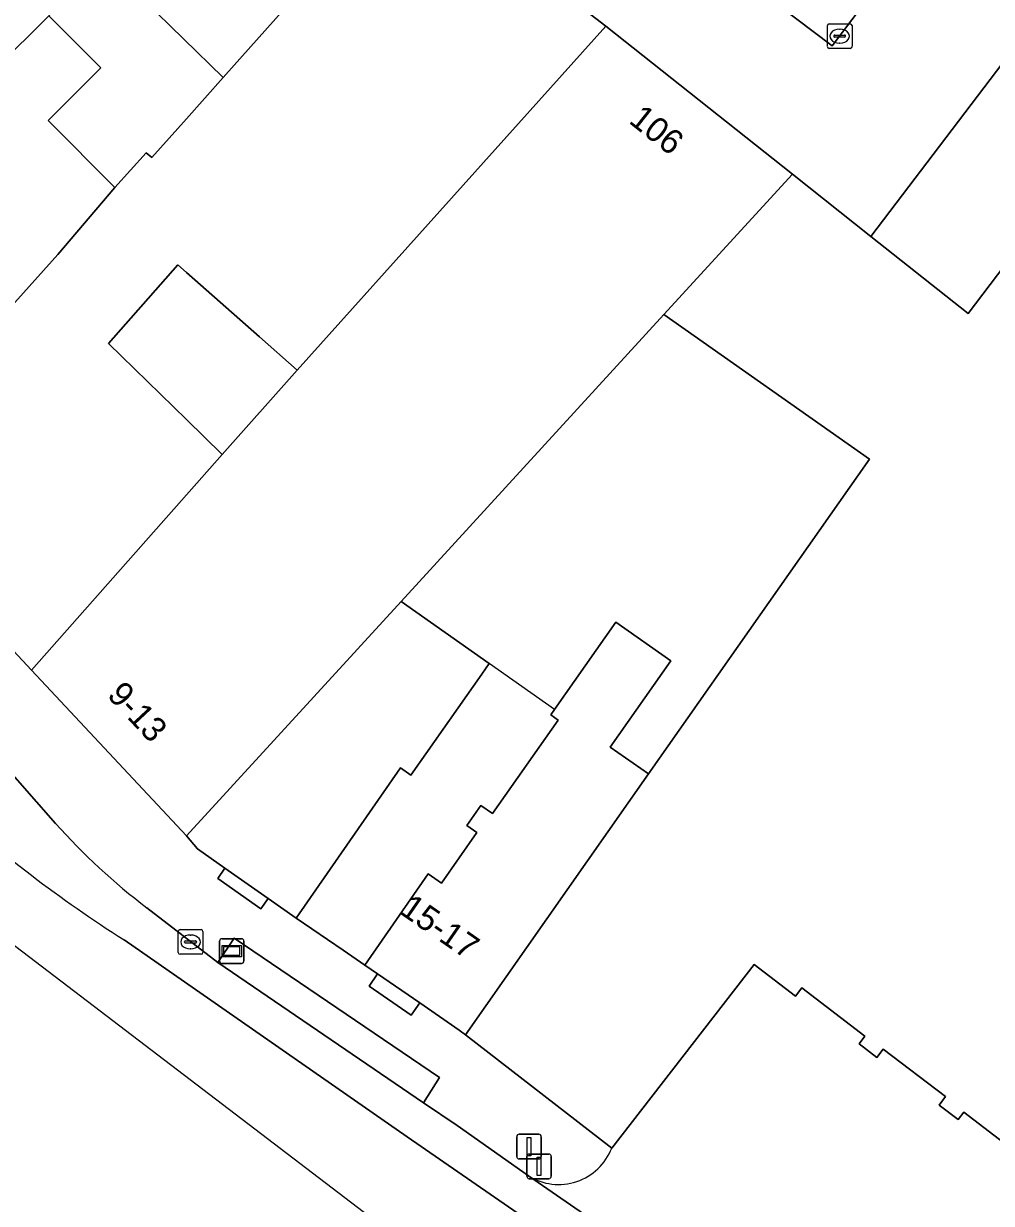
# Model space of a CAD drawing. Extents: x 160663 to 161506, y 382245 to 383291.
# Drawn here: x 160993.39 to 161032.66, y 382793.4 to 382841.23 of the extents above; entities that cross this region are included whole.
import ezdxf

# ---------------------------------------------------------------- set-up
doc = ezdxf.new("R2010")
doc.units = 0
for name, color, linetype in [('IMGEO_Erf', 7, 'Continuous'), ('IMGEO_Kolk', 7, 'Continuous'), ('IMGEO_Lichtmast', 7, 'Continuous'), ('IMGEO_Pand', 7, 'Continuous'), ('IMGEO_Pand_nummerreeks', 7, 'Continuous'), ('IMGEO_Pand_overbouw', 7, 'Continuous'), ('IMGEO_Parkeervlak_open', 7, 'Continuous'), ('IMGEO_Rijbaan_lokaal_gesloten', 7, 'Continuous'), ('IMGEO_Rijbaan_lokaal_open', 7, 'Continuous'), ('IMGEO_Verkeersregelinstallatiepaal', 7, 'Continuous'), ('IMGEO_Voetpad_open', 7, 'Continuous'), ('IMGEO_Wegwijzer', 7, 'Continuous')]:
    doc.layers.add(name, color=color, linetype=linetype)

msp = doc.modelspace()

# ---------------------------------------------------------------- linework, layer by layer
at = {"layer": 'IMGEO_Erf'}
for points in [[(161002.961, 382828.523), (161000, 382831.142), (160999.651, 382831.451), (160996.836, 382828.259), (161000, 382825.179), (161001.456, 382823.762), (161004.488, 382827.173)], [(161019.369, 382829.436), (161008.711, 382817.804), (161012.288, 382815.292), (161011.979, 382814.851), (161009.105, 382810.759), (161008.688, 382811.051), (161004.447, 382804.966), (161006.356, 382803.662), (161007.234, 382803.062), (161009.806, 382806.765), (161010.347, 382806.385), (161011.785, 382808.433), (161011.377, 382808.72), (161011.949, 382809.533), (161012.418, 382809.204), (161015.08, 382812.993), (161014.777, 382813.205), (161014.926, 382813.417), (161017.414, 382816.96), (161019.648, 382815.391), (161017.196, 382811.899), (161018.747, 382810.81), (161027.712, 382823.575)]]:
    msp.add_lwpolyline(points, close=True, dxfattribs=at)
at = {"layer": 'IMGEO_Kolk'}
for p, q in [((161026, 382840.292), (161026, 382841.144)), ((161026.075, 382841.218), (161026.927, 382841.218)), ((161026.488, 382840.998), (161026.513, 382840.998)), ((161027.001, 382841.144), (161027.001, 382840.292)), ((161026.259, 382840.712), (161026.259, 382840.724)), ((161026.697, 382840.675), (161026.299, 382840.675)), ((161026.302, 382840.761), (161026.7, 382840.761)), ((161026.511, 382840.438), (161026.486, 382840.438)), ((161026.743, 382840.724), (161026.743, 382840.712)), ((161026.927, 382840.218), (161026.075, 382840.218)), ((160999.668, 382803.57), (160999.668, 382804.422)), ((160999.743, 382804.496), (161000.595, 382804.496)), ((161000.669, 382804.422), (161000.669, 382803.57)), ((160999.927, 382803.99), (160999.927, 382804.002)), ((161000.365, 382803.953), (160999.967, 382803.953)), ((160999.97, 382804.039), (161000.368, 382804.039)), ((161000.156, 382804.276), (161000.181, 382804.276)), ((161000.411, 382804.002), (161000.411, 382803.99)), ((161000.595, 382803.496), (160999.743, 382803.496)), ((161000.179, 382803.716), (161000.154, 382803.716))]:
    msp.add_line(p, q, dxfattribs=at)
for points in [[(161026, 382840.292), (161026, 382841.144)], [(161026.075, 382841.218), (161026.927, 382841.218)], [(161027.001, 382841.144), (161027.001, 382840.292)], [(161026.927, 382840.218), (161026.075, 382840.218)], [(160999.668, 382803.57), (160999.668, 382804.422)], [(160999.743, 382804.496), (161000.595, 382804.496)], [(161000.669, 382804.422), (161000.669, 382803.57)], [(161000.595, 382803.496), (160999.743, 382803.496)]]:
    msp.add_lwpolyline(points, dxfattribs=at)
for centre, radius, start, end in [((161026.077, 382841.142), 0.0765, 91.552, 178.448), ((161026.077, 382841.142), 0.0765, 91.552, 178.448), ((161026.925, 382841.142), 0.0765, 1.552, 88.448), ((161026.925, 382841.142), 0.0765, 1.552, 88.448), ((161026.299, 382840.721), 0.0403, 85.8775, 175.7526), ((161026.296, 382840.711), 0.0366, 178.938, 274.7102), ((161026.7, 382840.718), 0.043, 264.8664, 352.4533), ((161026.704, 382840.723), 0.0386, 1.7309, 96.639), ((161026.077, 382840.294), 0.0765, 181.552, 268.448), ((161026.077, 382840.294), 0.0765, 181.552, 268.448), ((161026.925, 382840.294), 0.0765, 271.552, 358.448), ((161026.925, 382840.294), 0.0765, 271.552, 358.448), ((160999.745, 382804.42), 0.0765, 91.552, 178.448), ((160999.745, 382804.42), 0.0765, 91.552, 178.448), ((161000.593, 382804.42), 0.0765, 1.552, 88.448), ((161000.593, 382804.42), 0.0765, 1.552, 88.448), ((160999.967, 382803.999), 0.0403, 85.8775, 175.7526), ((160999.964, 382803.989), 0.0366, 178.938, 274.7102), ((161000.368, 382803.996), 0.043, 264.8664, 352.4533), ((161000.372, 382804.001), 0.0386, 1.7309, 96.639), ((160999.745, 382803.572), 0.0765, 181.552, 268.448), ((160999.745, 382803.572), 0.0765, 181.552, 268.448), ((161000.593, 382803.572), 0.0765, 271.552, 358.448), ((161000.593, 382803.572), 0.0765, 271.552, 358.448)]:
    msp.add_arc(centre, radius, start, end, dxfattribs=at)
for centre, major_axis, ratio, start_param, end_param in [((161026.487, 382840.718), (-0.387, 0.002), 0.722429, 4.712389, 7.853982), ((161026.512, 382840.718), (-0.39, 0.002), 0.717154, 1.570796, 4.712389), ((161000.155, 382803.996), (-0.387, 0.002), 0.722429, 4.712389, 7.853982), ((161000.18, 382803.996), (-0.39, 0.002), 0.717154, 1.570796, 4.712389)]:
    msp.add_ellipse(centre, major_axis=major_axis, ratio=ratio, start_param=start_param, end_param=end_param, dxfattribs=at)
at = {"layer": 'IMGEO_Lichtmast'}
for p, q in [((161013.909, 382795.399), (161014.699, 382795.399)), ((161014.699, 382795.399), (161013.909, 382795.399)), ((161013.809, 382794.499), (161013.809, 382795.299)), ((161013.809, 382795.299), (161013.809, 382794.499)), ((161014.799, 382795.299), (161014.799, 382794.499)), ((161014.799, 382794.499), (161014.799, 382795.299)), ((161014.699, 382794.399), (161013.909, 382794.399)), ((161013.909, 382794.399), (161014.699, 382794.399))]:
    msp.add_line(p, q, dxfattribs=at)
msp.add_lwpolyline([(161014.229, 382795.274), (161014.379, 382795.274), (161014.379, 382794.524), (161014.229, 382794.524), (161014.229, 382795.274)], dxfattribs=at)
for centre, start, end in [((161013.909, 382795.299), 90, 180), ((161013.909, 382795.299), 90, 180), ((161014.699, 382795.299), 0, 90), ((161014.699, 382795.299), 360, 90), ((161013.909, 382794.499), 180, 270), ((161013.909, 382794.499), 180, 270), ((161014.699, 382794.499), 270, 0), ((161014.699, 382794.499), 270, 0)]:
    msp.add_arc(centre, 0.1, start, end, dxfattribs=at)
at = {"layer": 'IMGEO_Pand'}
for points in [[(161017.015, 382841.125), (161015.219, 382842.521), (161009.04, 382847.522), (161005.762, 382843.842), (161001.492, 382839.047), (161000, 382837.371), (160998.598, 382835.797), (160998.363, 382835.992), (160997.101, 382834.576), (160994.79, 382831.866), (160986.529, 382822.664), (160992.244, 382816.582), (160993.712, 382815.013), (161001.456, 382823.762), (161000, 382825.179), (160996.836, 382828.259), (160999.651, 382831.451), (161000, 382831.142), (161002.961, 382828.523), (161004.488, 382827.173)], [(160987.939, 382843.74), (160976.696, 382832.495), (160979.771, 382829.42), (160982.946, 382826.246), (160986.529, 382822.664), (160994.79, 382831.866), (160997.101, 382834.576), (160994.393, 382837.303), (160996.522, 382839.439), (160994.42, 382841.542), (160992.264, 382839.415)], [(161019.369, 382829.436), (161024.581, 382835.124), (161017.015, 382841.125), (161004.488, 382827.173), (161001.456, 382823.762), (160993.712, 382815.013), (161000, 382808.297), (161008.711, 382817.804)], [(161000, 382808.297), (161000.45, 382807.767), (161001.563, 382806.987), (161003.312, 382805.761), (161004.447, 382804.966), (161008.688, 382811.051), (161009.105, 382810.759), (161011.979, 382814.851), (161012.288, 382815.292), (161008.711, 382817.804)], [(161011.319, 382800.229), (161018.747, 382810.81), (161017.196, 382811.899), (161019.648, 382815.391), (161017.414, 382816.96), (161014.926, 382813.417), (161014.777, 382813.205), (161015.08, 382812.993), (161012.418, 382809.204), (161011.949, 382809.533), (161011.377, 382808.72), (161011.785, 382808.433), (161010.347, 382806.385), (161009.806, 382806.765), (161007.234, 382803.062), (161007.754, 382802.704), (161009.465, 382801.526), (161011.068, 382800.423)]]:
    msp.add_lwpolyline(points, close=True, dxfattribs=at)
msp.add_lwpolyline([(161034.089, 382832.61), (161031.709, 382829.469), (161027.763, 382832.6), (161024.581, 382835.124), (161019.369, 382829.436), (161027.712, 382823.575), (161018.747, 382810.81), (161011.319, 382800.229), (161017.252, 382795.641), (161023.035, 382803.078), (161024.709, 382801.803), (161024.961, 382802.132), (161027.524, 382800.182), (161027.284, 382799.867), (161028.011, 382799.313), (161028.268, 382799.649), (161030.791, 382797.726), (161030.53, 382797.383), (161031.303, 382796.794), (161031.532, 382797.094), (161033.969, 382795.23)], dxfattribs=at)
at = {"layer": 'IMGEO_Pand_overbouw'}
msp.add_lwpolyline([(161014.926, 382813.417), (161012.288, 382815.292), (161011.979, 382814.851), (161009.105, 382810.759), (161008.688, 382811.051), (161004.447, 382804.966), (161006.356, 382803.662), (161007.234, 382803.062), (161009.806, 382806.765), (161010.347, 382806.385), (161011.785, 382808.433), (161011.377, 382808.72), (161011.949, 382809.533), (161012.418, 382809.204), (161015.08, 382812.993), (161014.777, 382813.205)], close=True, dxfattribs=at)
at = {"layer": 'IMGEO_Parkeervlak_open'}
for points in [[(161026.197, 382840.33), (161050.071, 382871.893), (161041.959, 382877.99), (161018.147, 382846.412)], [(160987.817, 382852.376), (160985.729, 382850.234), (160983.615, 382848.065), (160987.939, 382843.74), (160992.264, 382839.415), (160994.42, 382841.542), (160996.662, 382843.754)]]:
    msp.add_lwpolyline(points, close=True, dxfattribs=at)
for points in [[(161033.969, 382795.23), (161031.532, 382797.094), (161031.303, 382796.794), (161030.53, 382797.383), (161030.791, 382797.726), (161028.268, 382799.649), (161028.011, 382799.313), (161027.284, 382799.867), (161027.524, 382800.182), (161024.961, 382802.132), (161024.709, 382801.803), (161023.035, 382803.078), (161017.252, 382795.641)], [(161013.879, 382794.515), (161044.838, 382773.151)]]:
    msp.add_lwpolyline(points, dxfattribs=at)
msp.add_arc((161015.103, 382796.464), 2.301, 237.8645, 339.0564, dxfattribs=at)
at = {"layer": 'IMGEO_Rijbaan_lokaal_gesloten'}
for points in [[(160950.316, 382840.118), (160974.423, 382818.724), (160980.002, 382813.773), (161009.567, 382791.248), (161065.685, 382748.492), (161112.373, 382702.72), (161124.111, 382688.246), (161124.884, 382688.875), (161125.431, 382689.32), (161119.959, 382696.204), (161110.177, 382707.994), (161100.346, 382719.084), (161091.915, 382728.357), (161081.993, 382739.308), (161076.263, 382745.226), (161069.695, 382751.517), (161061.87, 382758.6), (161056.466, 382763.168), (161050.271, 382767.641), (161037.554, 382776.355), (161008.954, 382796.101), (160997.473, 382804.081)], [(160994.69, 382808.801), (160990.052, 382814.074), (160987.005, 382813.909)], [(161054.593, 382766.457), (161051.131, 382768.848), (161044.838, 382773.151), (161013.879, 382794.515), (161010.987, 382796.553), (161009.619, 382797.479), (161001.276, 382803.164), (160998.4, 382805.376)], [(160997.473, 382804.081), (161008.954, 382796.101), (161037.554, 382776.355), (161050.271, 382767.641), (161056.466, 382763.168), (161061.87, 382758.6), (161069.695, 382751.517), (161076.263, 382745.226), (161081.993, 382739.308), (161091.915, 382728.357), (161100.346, 382719.084), (161110.177, 382707.994), (161119.959, 382696.204), (161125.431, 382689.32), (161126.618, 382690.286), (161119.692, 382699.024)]]:
    msp.add_lwpolyline(points, dxfattribs=at)
for centre, radius, start, end in [((161025.476, 382848.237), 52.287, 227.5619, 237.6181), ((161025.476, 382848.237), 52.287, 227.5619, 237.6181), ((161014.959, 382827.034), 27.263, 221.9741, 232.6008)]:
    msp.add_arc(centre, radius, start, end, dxfattribs=at)
at = {"layer": 'IMGEO_Rijbaan_lokaal_open'}
for points in [[(161031.451, 382891.801), (161029.397, 382893.332), (161021.429, 382899.354), (161021.072, 382900.069), (161015.099, 382897.458), (161014.607, 382897.256), (161019.667, 382893.047), (161023.576, 382889.795), (161000, 382858.557), (160999.119, 382857.39), (161000, 382856.514), (161009.04, 382847.522), (161015.219, 382842.521), (161017.015, 382841.125), (161024.581, 382835.124), (161027.763, 382832.6), (161061.31, 382876.723)], [(160987.817, 382852.376), (160996.662, 382843.754), (161001.492, 382839.047), (161005.762, 382843.842), (161001.149, 382847.95), (160992.626, 382856.489), (160990.417, 382861.086), (160990.918, 382863.091), (160993.888, 382867.215), (160999.832, 382875.47), (161008.193, 382885.524), (161009.918, 382884.242)]]:
    msp.add_lwpolyline(points, dxfattribs=at)
msp.add_lwpolyline([(161041.959, 382877.99), (161050.071, 382871.893), (161026.197, 382840.33), (161018.147, 382846.412)], close=True, dxfattribs=at)
at = {"layer": 'IMGEO_Verkeersregelinstallatiepaal'}
for p, q in [((161013.402, 382795.301), (161013.402, 382796.101)), ((161013.402, 382796.101), (161013.402, 382795.301)), ((161013.502, 382796.201), (161014.292, 382796.201)), ((161014.292, 382796.201), (161013.502, 382796.201)), ((161014.392, 382796.101), (161014.392, 382795.301)), ((161014.392, 382795.301), (161014.392, 382796.101)), ((161014.292, 382795.201), (161013.502, 382795.201)), ((161013.502, 382795.201), (161014.292, 382795.201))]:
    msp.add_line(p, q, dxfattribs=at)
msp.add_lwpolyline([(161013.822, 382796.076), (161013.972, 382796.076), (161013.972, 382795.326), (161013.822, 382795.326), (161013.822, 382796.076)], dxfattribs=at)
for centre, start, end in [((161013.502, 382796.101), 90, 180), ((161013.502, 382796.101), 90, 180), ((161014.292, 382796.101), 0, 90), ((161014.292, 382796.101), 360, 90), ((161013.502, 382795.301), 180, 270), ((161013.502, 382795.301), 180, 270), ((161014.292, 382795.301), 270, 0), ((161014.292, 382795.301), 270, 0)]:
    msp.add_arc(centre, 0.1, start, end, dxfattribs=at)
at = {"layer": 'IMGEO_Voetpad_open'}
for points in [[(161052.966, 382858.403), (161053.444, 382858.047), (161053.485, 382858.1), (161065.315, 382873.613), (161061.31, 382876.723), (161027.763, 382832.6), (161031.709, 382829.469), (161034.089, 382832.61), (161033.688, 382832.928)], [(160996.662, 382843.754), (160994.42, 382841.542), (160996.522, 382839.439), (160994.393, 382837.303), (160997.101, 382834.576), (160998.363, 382835.992), (160998.598, 382835.797), (161000, 382837.371), (161001.492, 382839.047)], [(161001.563, 382806.987), (161001.268, 382806.568), (161003.015, 382805.339), (161003.312, 382805.761)], [(161001.276, 382803.164), (161009.619, 382797.479), (161010.267, 382798.495), (161001.942, 382804.156)], [(161007.754, 382802.704), (161007.409, 382802.207), (161009.117, 382801.025), (161009.465, 382801.526)]]:
    msp.add_lwpolyline(points, close=True, dxfattribs=at)
for points in [[(161017.252, 382795.641), (161011.319, 382800.229), (161011.068, 382800.423), (161009.465, 382801.526), (161009.117, 382801.025), (161007.409, 382802.207), (161007.754, 382802.704), (161007.234, 382803.062), (161006.356, 382803.662), (161004.447, 382804.966), (161003.312, 382805.761), (161003.015, 382805.339), (161001.268, 382806.568), (161001.563, 382806.987), (161000.45, 382807.767), (161000, 382808.297), (160993.712, 382815.013), (160992.244, 382816.582)], [(160990.052, 382814.074), (160994.69, 382808.801)], [(160998.4, 382805.376), (161001.276, 382803.164), (161001.942, 382804.156), (161010.267, 382798.495), (161009.619, 382797.479), (161010.987, 382796.553), (161013.879, 382794.515)]]:
    msp.add_lwpolyline(points, dxfattribs=at)
for centre, radius, start, end in [((161014.959, 382827.034), 27.263, 221.9741, 232.6008), ((161015.103, 382796.464), 2.301, 237.8645, 339.0564)]:
    msp.add_arc(centre, radius, start, end, dxfattribs=at)
at = {"layer": 'IMGEO_Wegwijzer'}
for p, q in [((161001.344, 382803.226), (161001.344, 382804.026)), ((161001.344, 382804.026), (161001.344, 382803.226)), ((161001.444, 382804.126), (161002.234, 382804.126)), ((161002.234, 382804.126), (161001.444, 382804.126)), ((161002.334, 382804.026), (161002.334, 382803.226)), ((161002.334, 382803.226), (161002.334, 382804.026)), ((161002.234, 382803.126), (161001.444, 382803.126)), ((161001.444, 382803.126), (161002.234, 382803.126))]:
    msp.add_line(p, q, dxfattribs=at)
for points in [[(161001.445, 382803.858), (161002.233, 382803.858), (161002.233, 382803.394), (161001.445, 382803.394), (161001.445, 382803.858)], [(161001.51, 382803.793), (161001.51, 382803.459), (161002.168, 382803.459), (161002.168, 382803.793), (161001.51, 382803.793)]]:
    msp.add_lwpolyline(points, dxfattribs=at)
for centre, start, end in [((161001.444, 382804.026), 90, 180), ((161001.444, 382804.026), 90, 180), ((161002.234, 382804.026), 0, 90), ((161002.234, 382804.026), 360, 90), ((161001.444, 382803.226), 180, 270), ((161001.444, 382803.226), 180, 270), ((161002.234, 382803.226), 270, 0), ((161002.234, 382803.226), 270, 0)]:
    msp.add_arc(centre, 0.1, start, end, dxfattribs=at)

# ---------------------------------------------------------------- texts
at = {"layer": 'IMGEO_Pand_nummerreeks'}
for s, rotation, p in [('106', 321.5775, (161017.904, 382837.23)), ('9-13', 313.1091, (160996.745, 382813.969)), ('15-17', 325.2582, (161008.6, 382805.181))]:
    msp.add_text(s, height=1, rotation=rotation, dxfattribs=at).set_placement(p)

doc.saveas('drawing.dxf')
